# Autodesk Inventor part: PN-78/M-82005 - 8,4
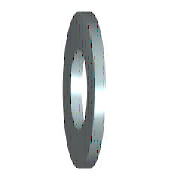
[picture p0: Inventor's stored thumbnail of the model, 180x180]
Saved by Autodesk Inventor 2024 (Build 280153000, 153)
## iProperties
Company: ATC
IsCustomPart: 0
Created: 2023-03
Part Number: PN-78/M-82005 - 8,4
Material: Stal, miękka
Description: Podkładki okrągłe, szereg nieobrobiony
Document SubType Name: Modeling
Standard: PN-78/M-82005
Designer: Andrzej Jaskulski
Standards Organization: PN
Language: pl-PL
Size Designation: 8,4
Categories: <MemberInstance><Categories><Category DisplayName="Mocowania" InternalName="e4da775c-781d-43d5-af7c-5136215cf5a6" Mnemonic="FSTN"><Category DisplayName="Podkład
Density: 7.85 g/cm^3
Appearance: Częściowo polerowany
Checked By: A.J.
Engr Approved By: Andrzej Jaskulski
Mfg Approved By: Andrzej Jaskulski
Authority: A.J.
Author: Andrzej Jaskulski
Title: A.J.: Kurs R2024-MEP
Revision Number: 1/24
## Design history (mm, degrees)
node "Bryła1"
sketch "Szkic"
  geometry: C1 r 8.5 at (0, 0); C2 r 4.2 at (0, 0); 1 further point
  constraints: 2 centre point, 2 coincident
  dimensions: "d0" = 8.4 diameter of C2 (= SD1); "d1" = 17 diameter of C1 (= SD2)
extrude "Bryła" new body sketch "Szkic" distance "d2" = 1.6 (= SD); taper "d3" = 0 deg
workaxis "Work Axis1"
workplane "Work Plane1"
node "Korpusy bryłowe"
node "Korpusy powierzchniowe"
other parameters: "SD1" = 8.4 [user parameter; used in 1 equation term], "SD2" = 17 [user parameter; used in 1 equation term], "SD" = 1.6 [user parameter; used in 1 equation term], "d4" = 0, "d5" = 0, "d6" = 0, "d7" = 0, "NND" = 8 [user parameter]
